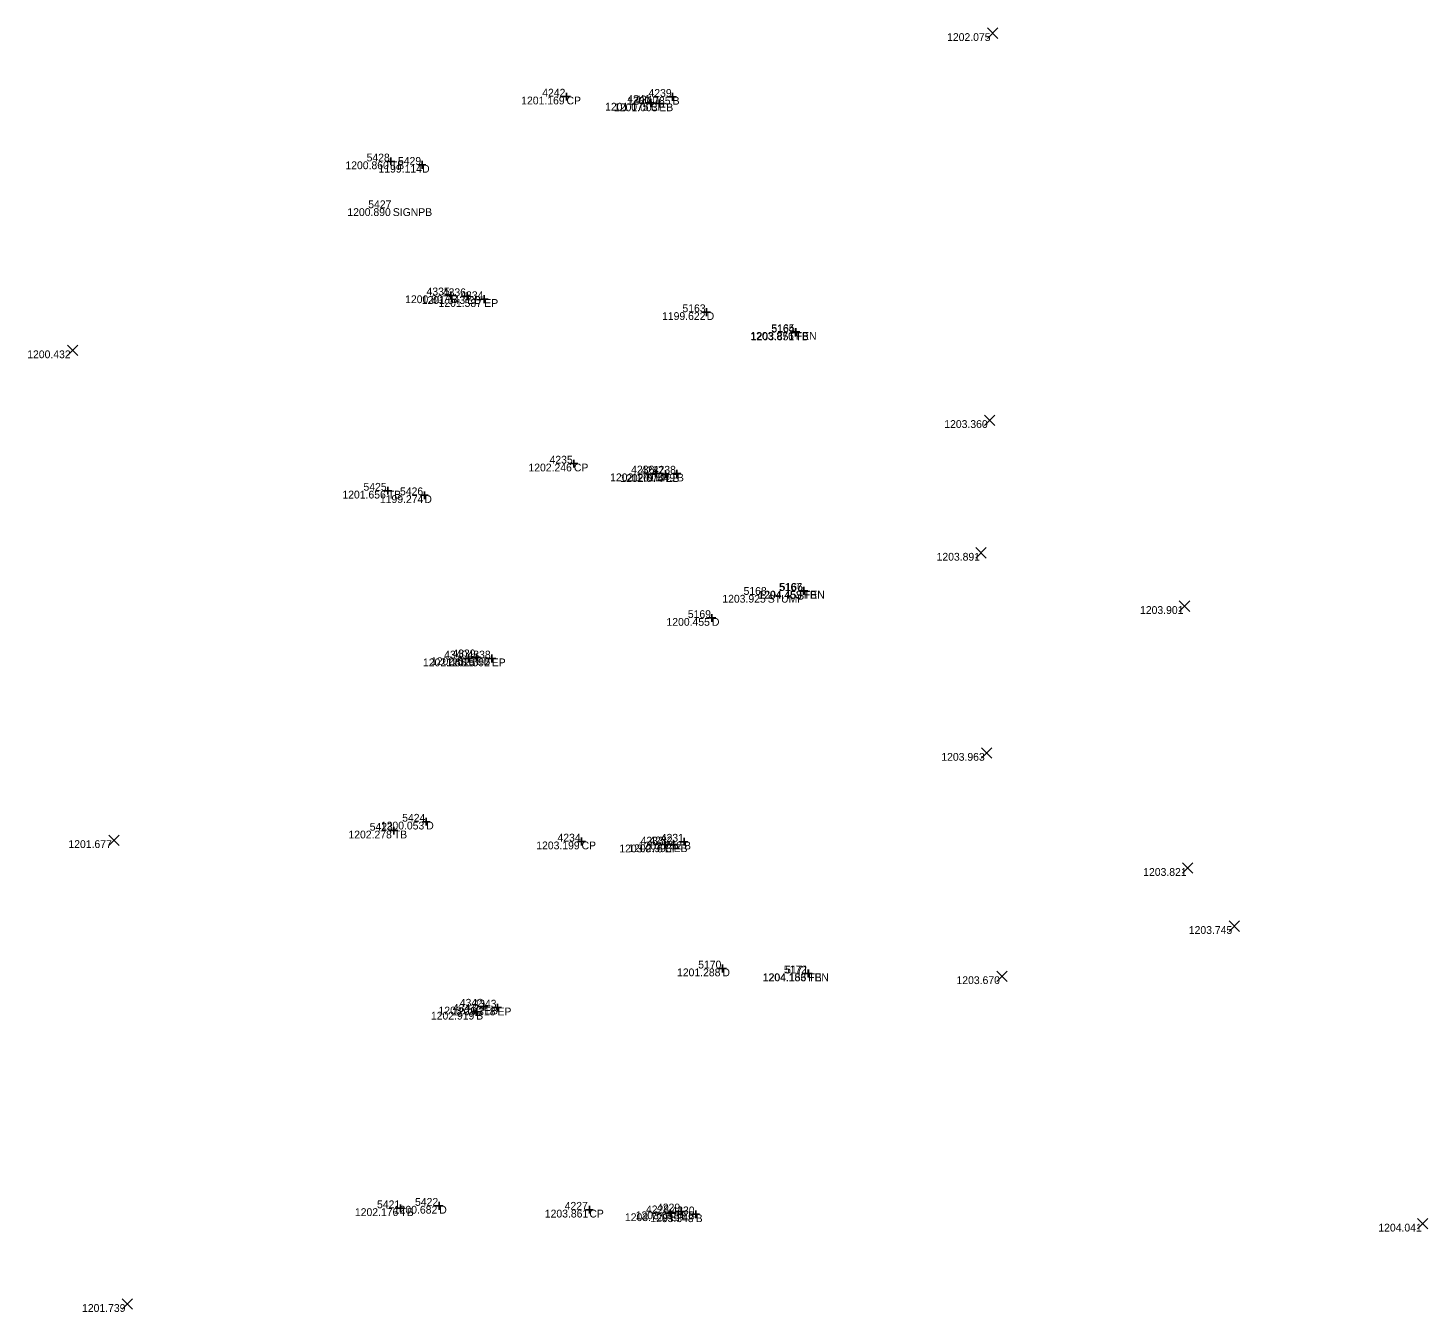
# Model space of a CAD drawing. Extents: x 2044997 to 2050342, y 455233 to 458054.
# Drawn here: x 2047553.3 to 2047733.1, y 457354.8 to 457519.7 of the extents above; entities that cross this region are included whole.
import ezdxf

# ---------------------------------------------------------------- set-up
doc = ezdxf.new("R2010")
doc.units = 0
for name, color, linetype in [('SV_X_Random_Point', 7, 'Continuous'), ('SV_X_Shot_Marker', 7, 'Continuous'), ('SV_X_Text_Comment', 7, 'Continuous'), ('SV_X_Text_Elevation', 7, 'Continuous'), ('SV_X_Text_Name', 7, 'Continuous')]:
    doc.layers.add(name, color=color, linetype=linetype)

msp = doc.modelspace()

# ---------------------------------------------------------------- linework, layer by layer
at = {"layer": 'SV_X_Random_Point'}
for p, q in [((2047676.52, 457518.35), (2047677.85, 457519.69)), ((2047676.52, 457519.69), (2047677.85, 457518.35)), ((2047558.35, 457477.63), (2047559.69, 457478.96)), ((2047558.35, 457478.96), (2047559.69, 457477.63)), ((2047676.15, 457468.67), (2047677.48, 457470)), ((2047676.15, 457470), (2047677.48, 457468.67)), ((2047675.04, 457451.63), (2047676.37, 457452.97)), ((2047675.04, 457452.97), (2047676.37, 457451.63)), ((2047701.17, 457444.79), (2047702.5, 457446.13)), ((2047701.17, 457446.13), (2047702.5, 457444.79)), ((2047675.75, 457425.94), (2047677.09, 457427.28)), ((2047675.75, 457427.28), (2047677.09, 457425.94)), ((2047563.69, 457414.74), (2047565.02, 457416.07)), ((2047563.69, 457416.07), (2047565.02, 457414.74)), ((2047701.58, 457411.16), (2047702.91, 457412.49)), ((2047701.58, 457412.49), (2047702.91, 457411.16)), ((2047707.57, 457403.71), (2047708.9, 457405.04)), ((2047707.57, 457405.04), (2047708.9, 457403.71)), ((2047677.73, 457397.27), (2047679.06, 457398.6)), ((2047677.73, 457398.6), (2047679.06, 457397.27)), ((2047731.78, 457365.5), (2047733.11, 457366.84)), ((2047731.78, 457366.84), (2047733.11, 457365.5)), ((2047565.38, 457355.19), (2047566.71, 457356.52)), ((2047565.38, 457356.52), (2047566.71, 457355.19))]:
    msp.add_line(p, q, dxfattribs=at)
at = {"layer": 'SV_X_Shot_Marker'}
for p, q in [((2047621.96, 457510.88), (2047622.96, 457510.88)), ((2047622.46, 457511.38), (2047622.46, 457510.38)), ((2047622.46, 457510.88), (2047622.46, 457510.88)), ((2047633.27, 457510.58), (2047633.27, 457509.58)), ((2047635.59, 457510.85), (2047636.59, 457510.85)), ((2047636.09, 457511.35), (2047636.09, 457510.35)), ((2047636.09, 457510.85), (2047636.09, 457510.85)), ((2047632.77, 457510.08), (2047633.77, 457510.08)), ((2047633.27, 457510.08), (2047633.27, 457510.08)), ((2047633.88, 457510), (2047634.88, 457510)), ((2047634.38, 457510.5), (2047634.38, 457509.5)), ((2047634.38, 457510), (2047634.38, 457510)), ((2047599.4, 457502.56), (2047600.4, 457502.56)), ((2047599.9, 457503.06), (2047599.9, 457502.06)), ((2047599.9, 457502.56), (2047599.9, 457502.56)), ((2047603.41, 457502.12), (2047604.41, 457502.12)), ((2047603.91, 457502.62), (2047603.91, 457501.62)), ((2047603.91, 457502.12), (2047603.91, 457502.12)), ((2047607.11, 457485.36), (2047608.11, 457485.36)), ((2047607.61, 457485.86), (2047607.61, 457484.86)), ((2047607.61, 457485.36), (2047607.61, 457485.36)), ((2047609.69, 457485.76), (2047609.69, 457484.76)), ((2047611.9, 457485.38), (2047611.9, 457484.38)), ((2047609.19, 457485.26), (2047610.19, 457485.26)), ((2047609.69, 457485.26), (2047609.69, 457485.26)), ((2047611.4, 457484.88), (2047612.4, 457484.88)), ((2047611.9, 457484.88), (2047611.9, 457484.88)), ((2047640.46, 457483.7), (2047640.46, 457482.7)), ((2047639.96, 457483.2), (2047640.96, 457483.2)), ((2047640.46, 457483.2), (2047640.46, 457483.2)), ((2047651.35, 457480.59), (2047652.35, 457480.59)), ((2047651.41, 457480.66), (2047652.41, 457480.66)), ((2047651.85, 457481.09), (2047651.85, 457480.09)), ((2047651.85, 457480.59), (2047651.85, 457480.59)), ((2047651.91, 457481.16), (2047651.91, 457480.16)), ((2047651.91, 457480.66), (2047651.91, 457480.66)), ((2047622.91, 457463.76), (2047623.91, 457463.76)), ((2047623.41, 457464.26), (2047623.41, 457463.26)), ((2047623.41, 457463.76), (2047623.41, 457463.76)), ((2047633.38, 457462.5), (2047634.38, 457462.5)), ((2047633.88, 457463), (2047633.88, 457462)), ((2047633.88, 457462.5), (2047633.88, 457462.5)), ((2047634.67, 457462.4), (2047635.67, 457462.4)), ((2047635.17, 457462.9), (2047635.17, 457461.9)), ((2047635.17, 457462.4), (2047635.17, 457462.4)), ((2047636.14, 457462.47), (2047637.14, 457462.47)), ((2047636.64, 457462.97), (2047636.64, 457461.97)), ((2047636.64, 457462.47), (2047636.64, 457462.47)), ((2047599.01, 457460.28), (2047600.01, 457460.28)), ((2047599.51, 457460.78), (2047599.51, 457459.78)), ((2047599.51, 457460.28), (2047599.51, 457460.28)), ((2047604.2, 457460.2), (2047604.2, 457459.2)), ((2047603.7, 457459.7), (2047604.7, 457459.7)), ((2047604.2, 457459.7), (2047604.2, 457459.7)), ((2047652.9, 457447.9), (2047652.9, 457446.9)), ((2047652.95, 457447.94), (2047652.95, 457446.94)), ((2047652.4, 457447.4), (2047653.4, 457447.4)), ((2047652.45, 457447.44), (2047653.45, 457447.44)), ((2047652.9, 457447.4), (2047652.9, 457447.4)), ((2047652.95, 457447.44), (2047652.95, 457447.44)), ((2047641.14, 457444.44), (2047641.14, 457443.44)), ((2047640.64, 457443.94), (2047641.64, 457443.94)), ((2047641.14, 457443.94), (2047641.14, 457443.94)), ((2047609.37, 457438.74), (2047610.37, 457438.74)), ((2047609.87, 457439.24), (2047609.87, 457438.24)), ((2047609.87, 457438.74), (2047609.87, 457438.74)), ((2047610.4, 457438.89), (2047611.4, 457438.89)), ((2047610.9, 457439.39), (2047610.9, 457438.39)), ((2047610.9, 457438.89), (2047610.9, 457438.89)), ((2047612.36, 457438.74), (2047613.36, 457438.74)), ((2047612.86, 457439.24), (2047612.86, 457438.24)), ((2047612.86, 457438.74), (2047612.86, 457438.74)), ((2047600.28, 457417.14), (2047600.28, 457416.14)), ((2047603.94, 457417.79), (2047604.94, 457417.79)), ((2047604.44, 457418.29), (2047604.44, 457417.29)), ((2047604.44, 457417.79), (2047604.44, 457417.79)), ((2047599.78, 457416.64), (2047600.78, 457416.64)), ((2047600.28, 457416.64), (2047600.28, 457416.64)), ((2047623.89, 457415.24), (2047624.89, 457415.24)), ((2047624.39, 457415.74), (2047624.39, 457414.74)), ((2047624.39, 457415.24), (2047624.39, 457415.24)), ((2047635.08, 457415.35), (2047635.08, 457414.35)), ((2047636.22, 457415.38), (2047636.22, 457414.38)), ((2047637.06, 457415.22), (2047638.06, 457415.22)), ((2047637.56, 457415.72), (2047637.56, 457414.72)), ((2047637.56, 457415.22), (2047637.56, 457415.22)), ((2047634.58, 457414.85), (2047635.58, 457414.85)), ((2047635.08, 457414.85), (2047635.08, 457414.85)), ((2047635.72, 457414.88), (2047636.72, 457414.88)), ((2047636.22, 457414.88), (2047636.22, 457414.88)), ((2047642.49, 457399.44), (2047642.49, 457398.44)), ((2047641.99, 457398.94), (2047642.99, 457398.94)), ((2047642.49, 457398.94), (2047642.49, 457398.94)), ((2047652.98, 457398.31), (2047653.98, 457398.31)), ((2047653.03, 457398.3), (2047654.03, 457398.3)), ((2047653.48, 457398.81), (2047653.48, 457397.81)), ((2047653.48, 457398.31), (2047653.48, 457398.31)), ((2047653.53, 457398.8), (2047653.53, 457397.8)), ((2047653.53, 457398.3), (2047653.53, 457398.3)), ((2047610.86, 457393.88), (2047610.86, 457392.88)), ((2047611.36, 457394.04), (2047612.36, 457394.04)), ((2047611.86, 457394.54), (2047611.86, 457393.54)), ((2047611.86, 457394.04), (2047611.86, 457394.04)), ((2047613.1, 457393.92), (2047614.1, 457393.92)), ((2047613.6, 457394.42), (2047613.6, 457393.42)), ((2047613.6, 457393.92), (2047613.6, 457393.92)), ((2047610.36, 457393.38), (2047611.36, 457393.38)), ((2047610.86, 457393.38), (2047610.86, 457393.38)), ((2047601.12, 457368.66), (2047601.12, 457367.66)), ((2047605.61, 457368.47), (2047606.61, 457368.47)), ((2047606.11, 457368.97), (2047606.11, 457367.97)), ((2047606.11, 457368.47), (2047606.11, 457368.47)), ((2047625.39, 457368.47), (2047625.39, 457367.47)), ((2047600.62, 457368.16), (2047601.62, 457368.16)), ((2047601.12, 457368.16), (2047601.12, 457368.16)), ((2047624.89, 457367.97), (2047625.89, 457367.97)), ((2047625.39, 457367.97), (2047625.39, 457367.97)), ((2047635.28, 457367.51), (2047636.28, 457367.51)), ((2047635.78, 457368.01), (2047635.78, 457367.01)), ((2047635.78, 457367.51), (2047635.78, 457367.51)), ((2047636.68, 457367.75), (2047637.68, 457367.75)), ((2047637.18, 457368.25), (2047637.18, 457367.25)), ((2047637.18, 457367.75), (2047637.18, 457367.75)), ((2047638.55, 457367.38), (2047639.55, 457367.38)), ((2047639.05, 457367.88), (2047639.05, 457366.88)), ((2047639.05, 457367.38), (2047639.05, 457367.38))]:
    msp.add_line(p, q, dxfattribs=at)

# ---------------------------------------------------------------- texts
at = {"layer": 'SV_X_Text_Comment'}
for s, p in [('CP', (2047622.46, 457509.88)), ('B', (2047636.09, 457509.85)), ('EP', (2047633.27, 457509.08)), ('EB', (2047634.38, 457509)), ('TB', (2047599.9, 457501.56)), ('D', (2047603.91, 457501.12)), ('SIGNPB', (2047600.15, 457495.55)), ('B', (2047607.61, 457484.36)), ('EB', (2047609.69, 457484.26)), ('EP', (2047611.9, 457483.88)), ('D', (2047640.46, 457482.2)), ('TB', (2047651.85, 457479.59)), ('FEN', (2047651.91, 457479.66)), ('CP', (2047623.41, 457462.76)), ('EP', (2047633.88, 457461.5)), ('EB', (2047635.17, 457461.4)), ('B', (2047636.64, 457461.47)), ('TB', (2047599.51, 457459.28)), ('D', (2047604.2, 457458.7)), ('STUMP', (2047648.31, 457445.91)), ('TB', (2047652.9, 457446.4)), ('FEN', (2047652.95, 457446.44)), ('D', (2047641.14, 457442.94)), ('B', (2047609.87, 457437.74)), ('EB', (2047610.9, 457437.89)), ('EP', (2047612.86, 457437.74)), ('D', (2047604.44, 457416.79)), ('TB', (2047600.28, 457415.64)), ('CP', (2047624.39, 457414.24)), ('B', (2047637.56, 457414.22)), ('EP', (2047635.08, 457413.85)), ('EB', (2047636.22, 457413.88)), ('D', (2047642.49, 457397.94)), ('TB', (2047653.53, 457397.3)), ('FEN', (2047653.48, 457397.31)), ('EB', (2047611.86, 457393.04)), ('EP', (2047613.6, 457392.92)), ('B', (2047610.86, 457392.38)), ('D', (2047606.11, 457367.47)), ('TB', (2047601.12, 457367.16)), ('CP', (2047625.39, 457366.97)), ('EP', (2047635.78, 457366.51)), ('EB', (2047637.18, 457366.75)), ('B', (2047639.05, 457366.38))]:
    msp.add_text(s, height=1, dxfattribs=at).set_placement(p)
at = {"layer": 'SV_X_Text_Elevation'}
for s, p in [('1202.075', (2047671.34, 457518.02)), ('1201.169', (2047616.64, 457509.88)), ('1200.785', (2047630.25, 457509.85)), ('1201.075', (2047627.42, 457509.08)), ('1201.003', (2047628.56, 457509)), ('1200.860', (2047594.06, 457501.56)), ('1199.114', (2047598.31, 457501.12)), ('1200.890', (2047594.31, 457495.55)), ('1200.807', (2047601.73, 457484.36)), ('1201.543', (2047603.86, 457484.26)), ('1201.587', (2047606.02, 457483.88)), ('1199.622', (2047634.73, 457482.2)), ('1203.876', (2047646.07, 457479.66)), ('1203.851', (2047646.13, 457479.59)), ('1200.432', (2047553.19, 457477.29)), ('1203.360', (2047670.98, 457468.34)), ('1202.246', (2047617.57, 457462.76)), ('1202.179', (2047628.06, 457461.5)), ('1202.074', (2047629.36, 457461.4)), ('1201.849', (2047630.83, 457461.47)), ('1201.656', (2047593.67, 457459.28)), ('1199.274', (2047598.49, 457458.7)), ('1203.891', (2047669.99, 457451.3)), ('1203.925', (2047642.47, 457445.91)), ('1204.453', (2047647.07, 457446.4)), ('1204.459', (2047647.13, 457446.44)), ('1203.901', (2047696.12, 457444.46)), ('1200.455', (2047635.3, 457442.94)), ('1202.065', (2047604.02, 457437.74)), ('1202.515', (2047605.05, 457437.89)), ('1202.592', (2047607.03, 457437.74)), ('1203.963', (2047670.6, 457425.61)), ('1200.053', (2047598.61, 457416.79)), ('1201.677', (2047558.48, 457414.41)), ('1202.278', (2047594.45, 457415.64)), ('1203.199', (2047618.57, 457414.24)), ('1202.752', (2047631.72, 457414.22)), ('1203.076', (2047629.24, 457413.85)), ('1202.993', (2047630.39, 457413.88)), ('1203.821', (2047696.53, 457410.83)), ('1203.745', (2047702.39, 457403.38)), ('1201.288', (2047636.65, 457397.94)), ('1204.183', (2047647.65, 457397.31)), ('1204.156', (2047647.69, 457397.3)), ('1203.670', (2047672.55, 457396.94)), ('1203.260', (2047606.02, 457393.04)), ('1203.318', (2047607.76, 457392.92)), ('1202.919', (2047605.04, 457392.38)), ('1200.682', (2047600.28, 457367.47)), ('1202.176', (2047595.28, 457367.16)), ('1203.861', (2047619.67, 457366.97)), ('1203.729', (2047629.96, 457366.51)), ('1203.658', (2047631.34, 457366.75)), ('1203.348', (2047633.21, 457366.38)), ('1204.041', (2047726.73, 457365.17)), ('1201.739', (2047560.23, 457354.85))]:
    msp.add_text(s, height=1, dxfattribs=at).set_placement(p)
at = {"layer": 'SV_X_Text_Name'}
for s, p in [('4242', (2047619.34, 457510.88)), ('4241', (2047630.27, 457510.08)), ('4240', (2047631.26, 457510)), ('4239', (2047632.99, 457510.85)), ('5428', (2047596.78, 457502.56)), ('5429', (2047600.81, 457502.12)), ('5427', (2047596.99, 457496.55)), ('4335', (2047604.48, 457485.36)), ('4336', (2047606.57, 457485.26)), ('4334', (2047608.81, 457484.88)), ('5163', (2047637.35, 457483.2)), ('5164', (2047648.76, 457480.59)), ('5165', (2047648.78, 457480.66)), ('4235', (2047620.28, 457463.76)), ('4236', (2047630.76, 457462.5)), ('4237', (2047632.01, 457462.4)), ('4238', (2047633.53, 457462.47)), ('5425', (2047596.38, 457460.28)), ('5426', (2047601.07, 457459.7)), ('5168', (2047645.2, 457446.91)), ('5167', (2047649.74, 457447.4)), ('5166', (2047649.83, 457447.44)), ('5169', (2047638.04, 457443.94)), ('4340', (2047606.75, 457438.74)), ('4339', (2047607.8, 457438.89)), ('4338', (2047609.74, 457438.74)), ('5424', (2047601.35, 457417.79)), ('5423', (2047597.18, 457416.64)), ('4234', (2047621.3, 457415.24)), ('4233', (2047631.97, 457414.85)), ('4232', (2047633.1, 457414.88)), ('4231', (2047634.56, 457415.22)), ('5170', (2047639.37, 457398.94)), ('5172', (2047650.37, 457398.31)), ('5171', (2047650.54, 457398.3)), ('4341', (2047607.86, 457393.38)), ('4342', (2047608.75, 457394.04)), ('4343', (2047610.49, 457393.92)), ('5421', (2047598.12, 457368.16)), ('5422', (2047603, 457368.47)), ('4227', (2047622.22, 457367.97)), ('4228', (2047632.66, 457367.51)), ('4229', (2047634.08, 457367.75)), ('4230', (2047635.93, 457367.38))]:
    msp.add_text(s, height=1, dxfattribs=at).set_placement(p)

doc.saveas('drawing.dxf')
